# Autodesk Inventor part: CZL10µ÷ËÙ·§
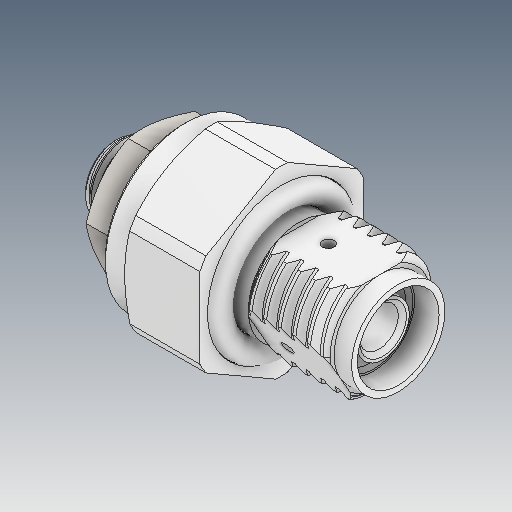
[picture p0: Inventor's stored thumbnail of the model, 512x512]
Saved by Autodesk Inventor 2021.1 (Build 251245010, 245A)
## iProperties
Created: 2021-05
Part Number: CZL10µ÷ËÙ·§
Material: Ogólny
Document SubType Name: Modeling
Designer: user
Density: 1 g/cm^3
Appearance: Domyślna
Author: user
Revision Number: ÈÎºÎ
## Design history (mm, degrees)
feature "ÊäÈë1"
feature "ÊäÈë2"
feature "ÊäÈë4"
node "Bryła1"
node "Bryła2"
node "Bryła3"
